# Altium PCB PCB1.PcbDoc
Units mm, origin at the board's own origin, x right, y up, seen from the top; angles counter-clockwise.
Board outline 69.22 x 64.13 mm, 4 copper layers (Top Layer, Int1 (GND), Int2 (PWR), Bottom Layer), stack 1.591 mm thick; 51 components, 53 nets, 197 pads, 100 vias.
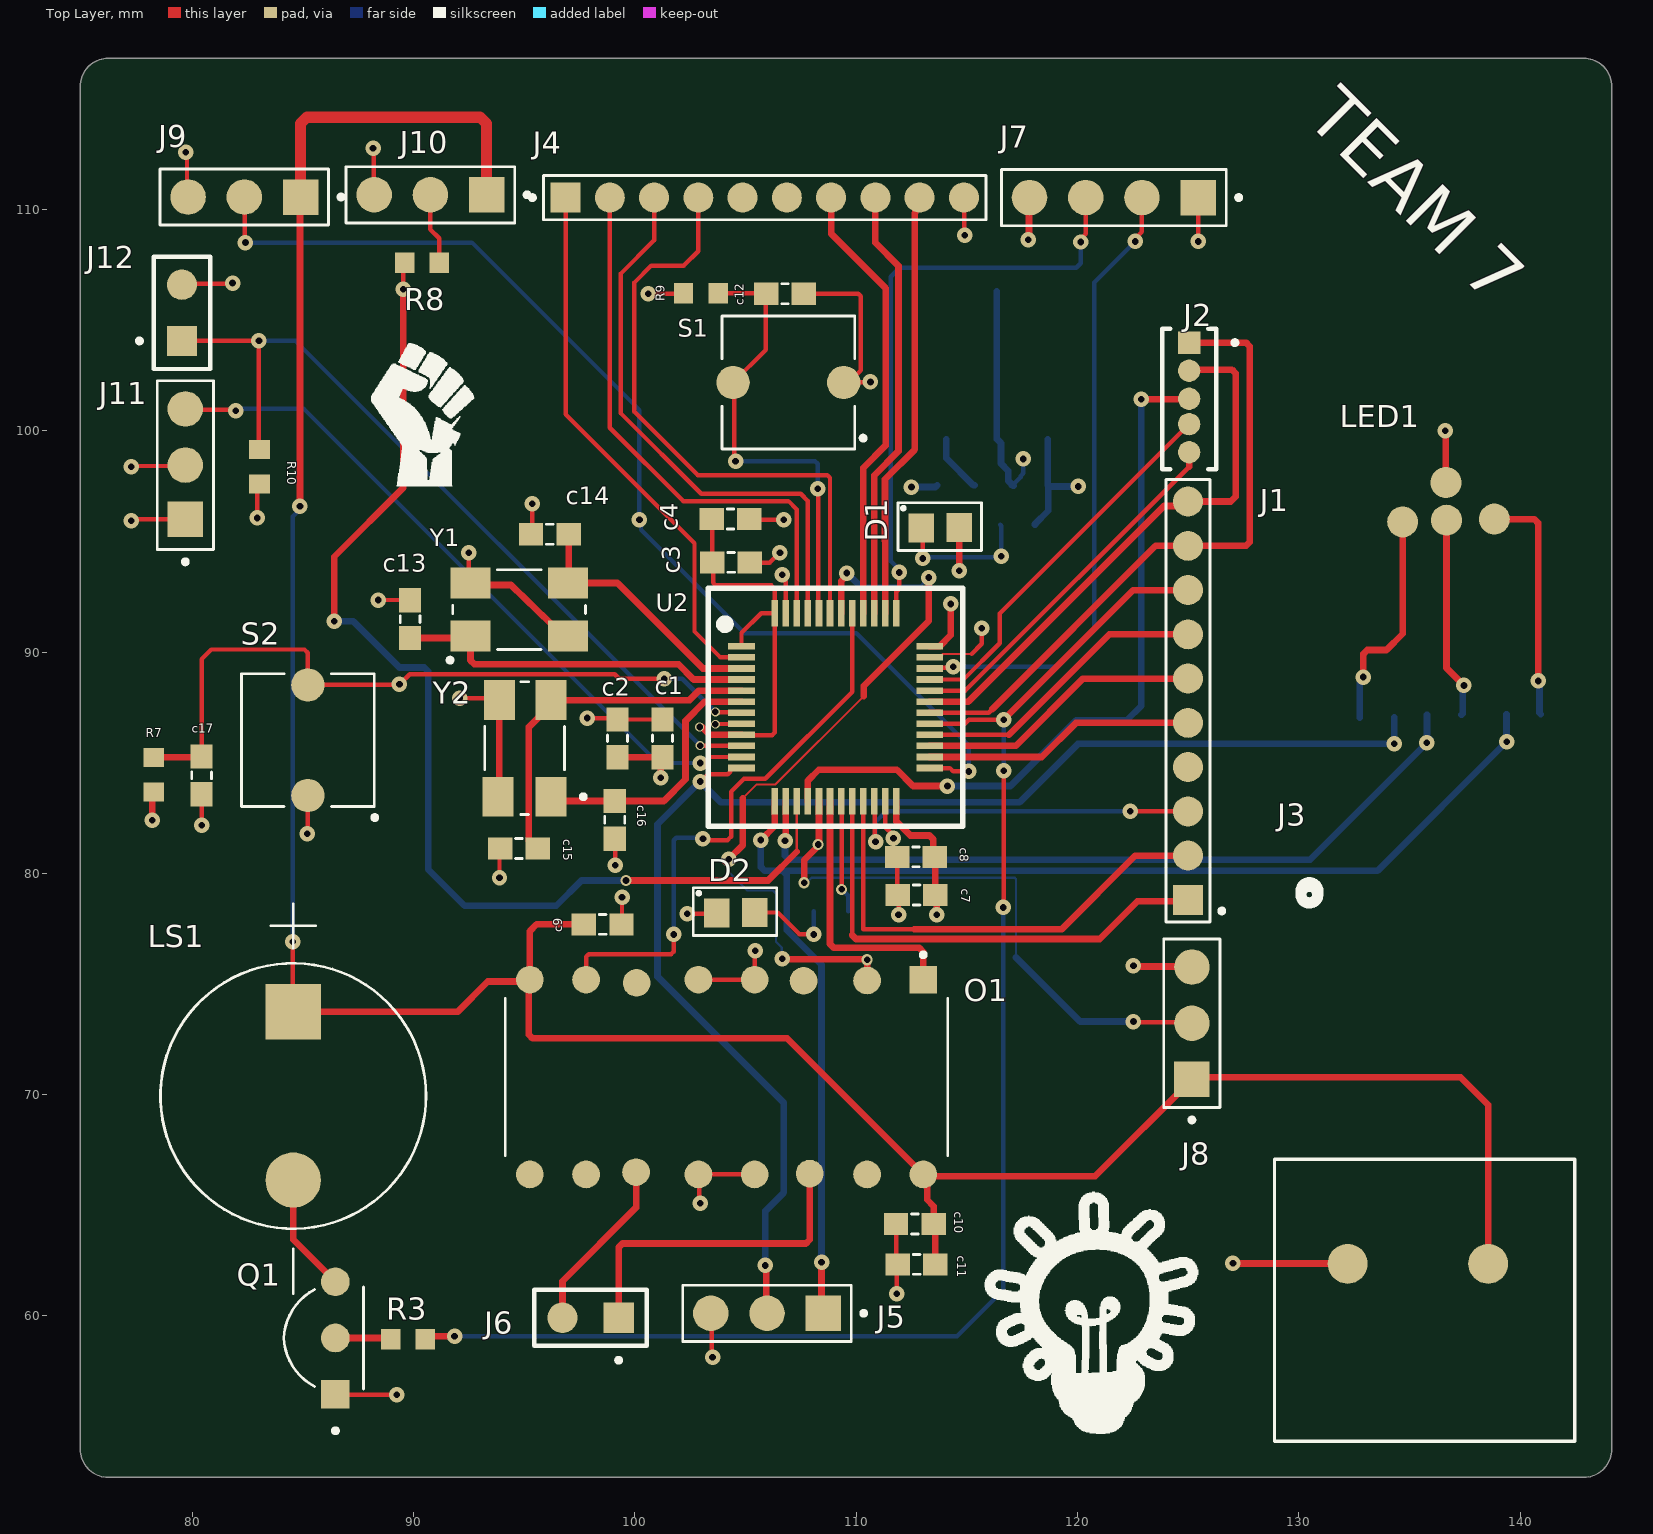
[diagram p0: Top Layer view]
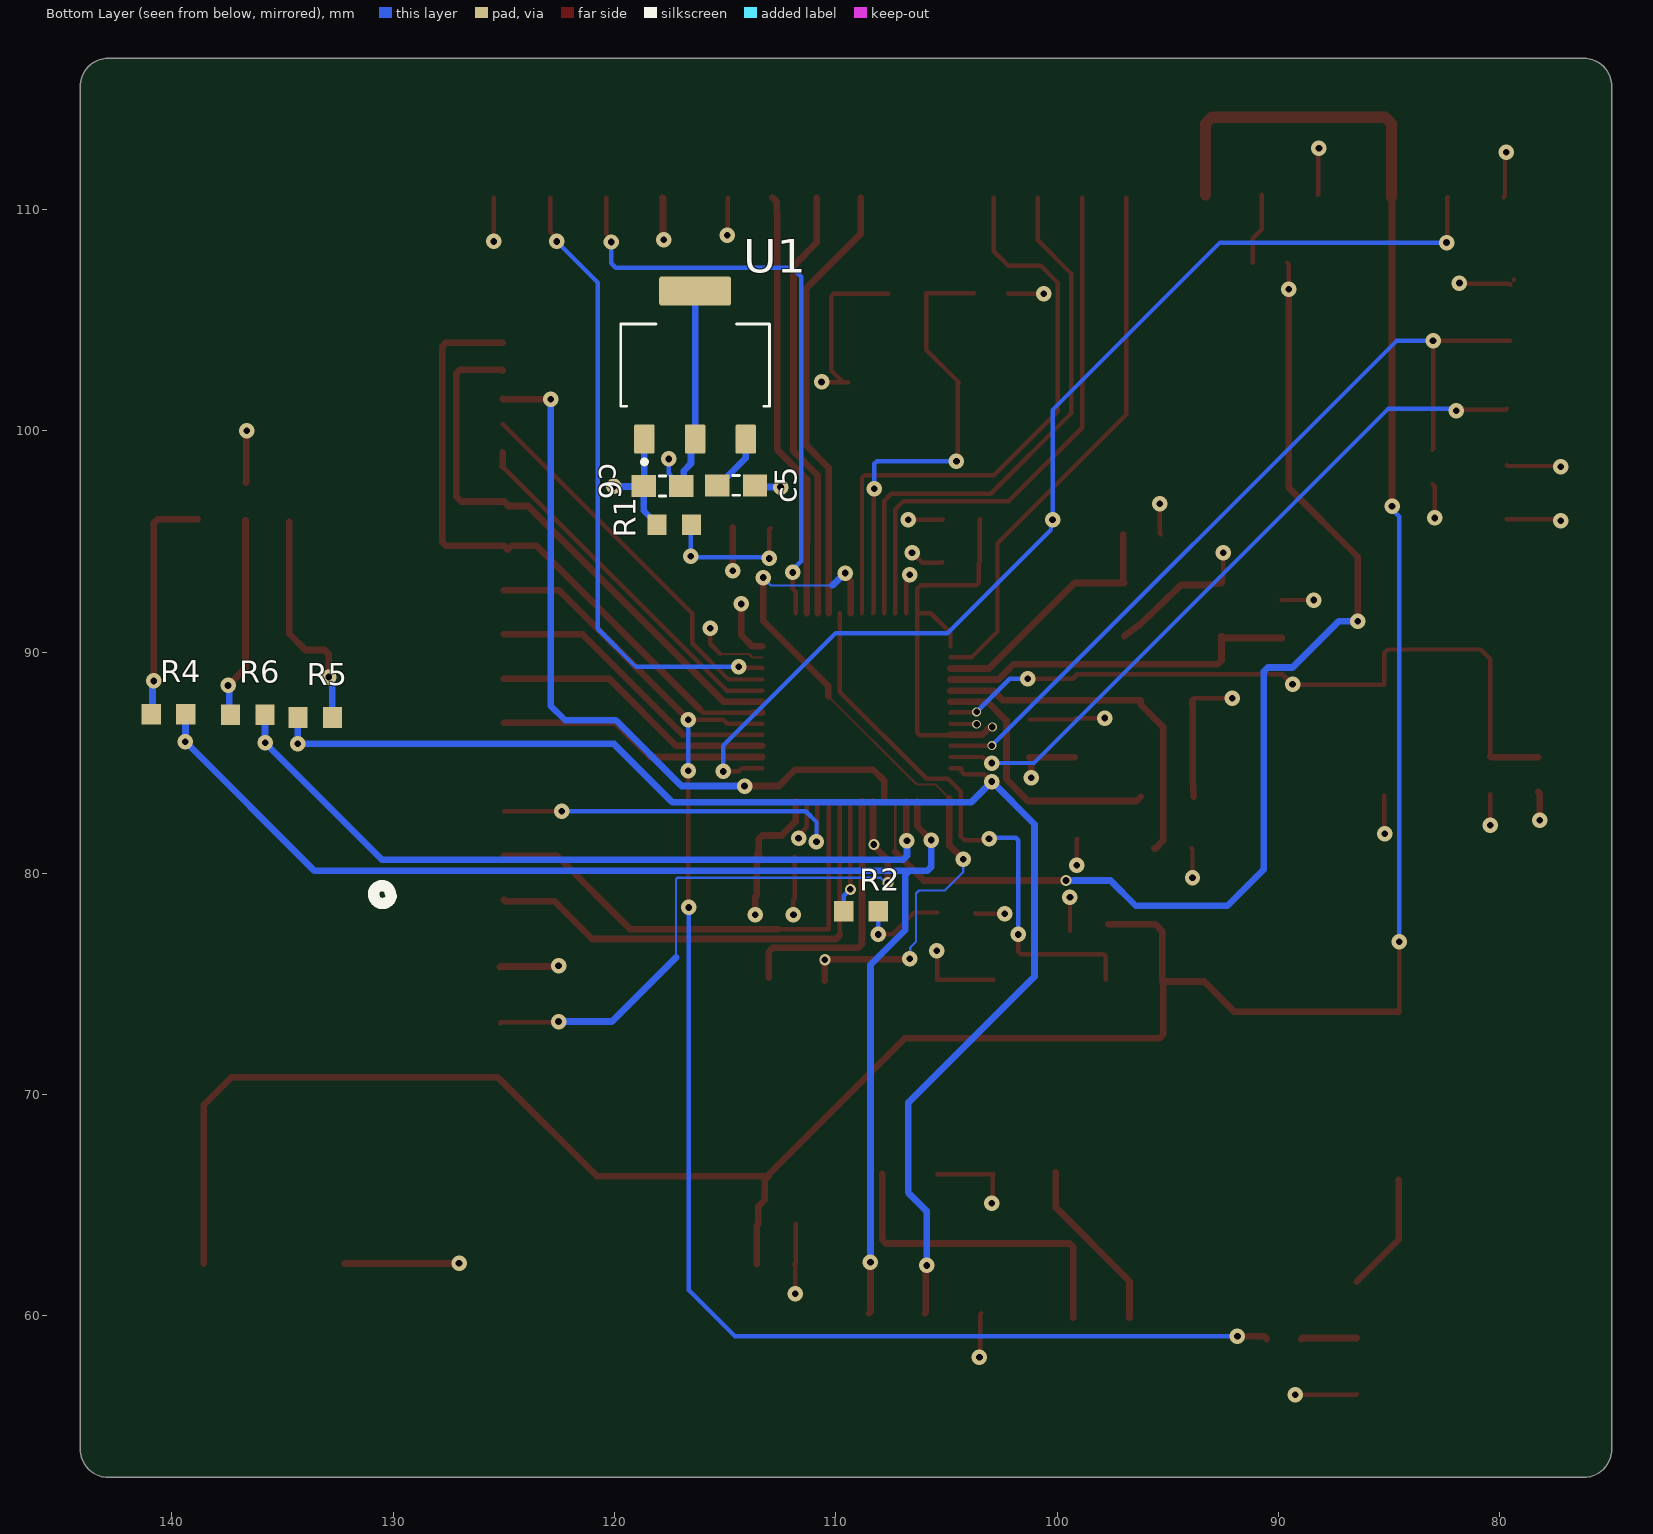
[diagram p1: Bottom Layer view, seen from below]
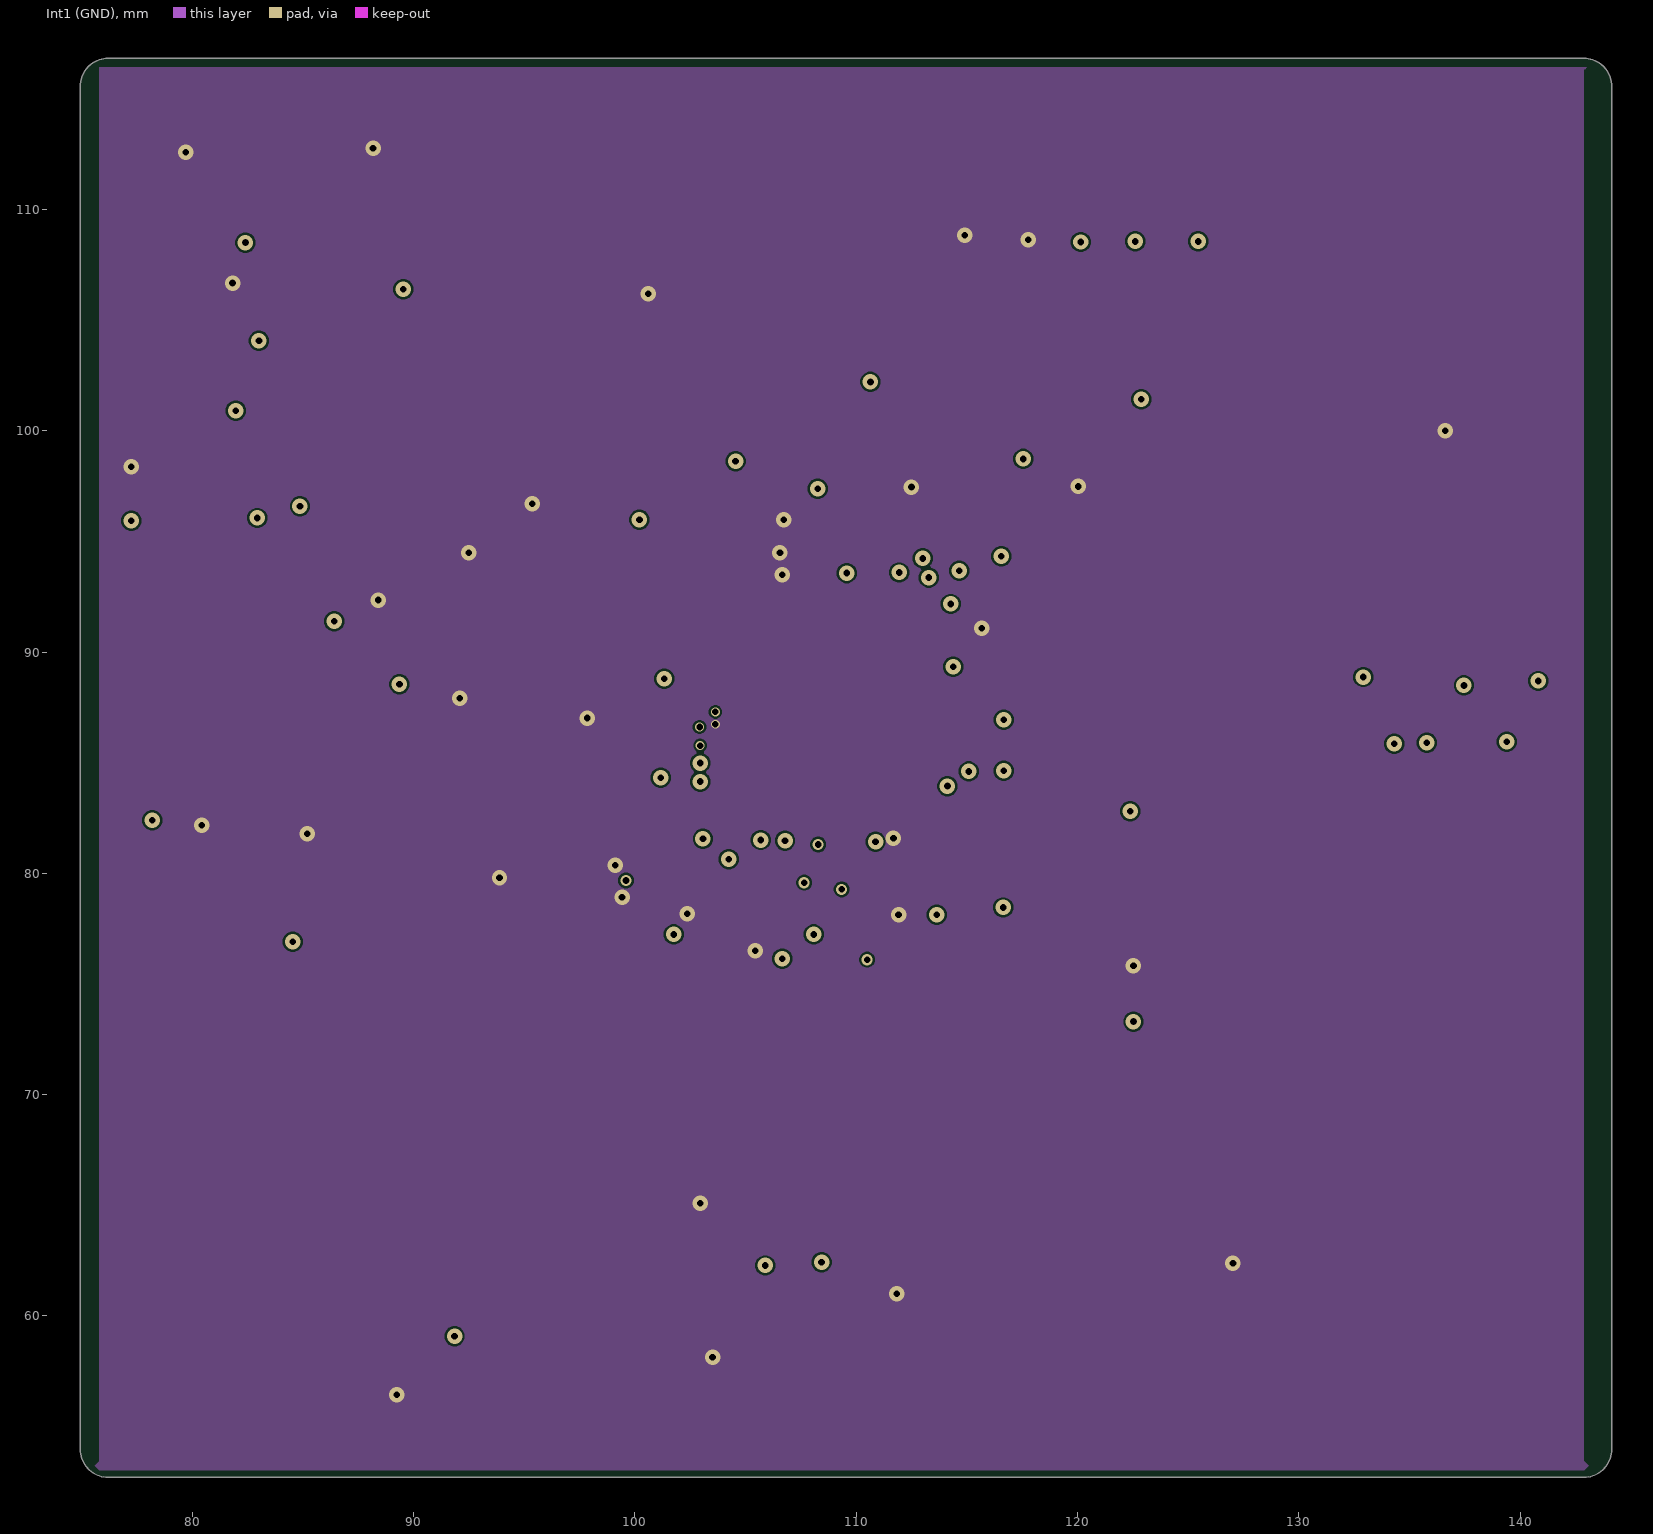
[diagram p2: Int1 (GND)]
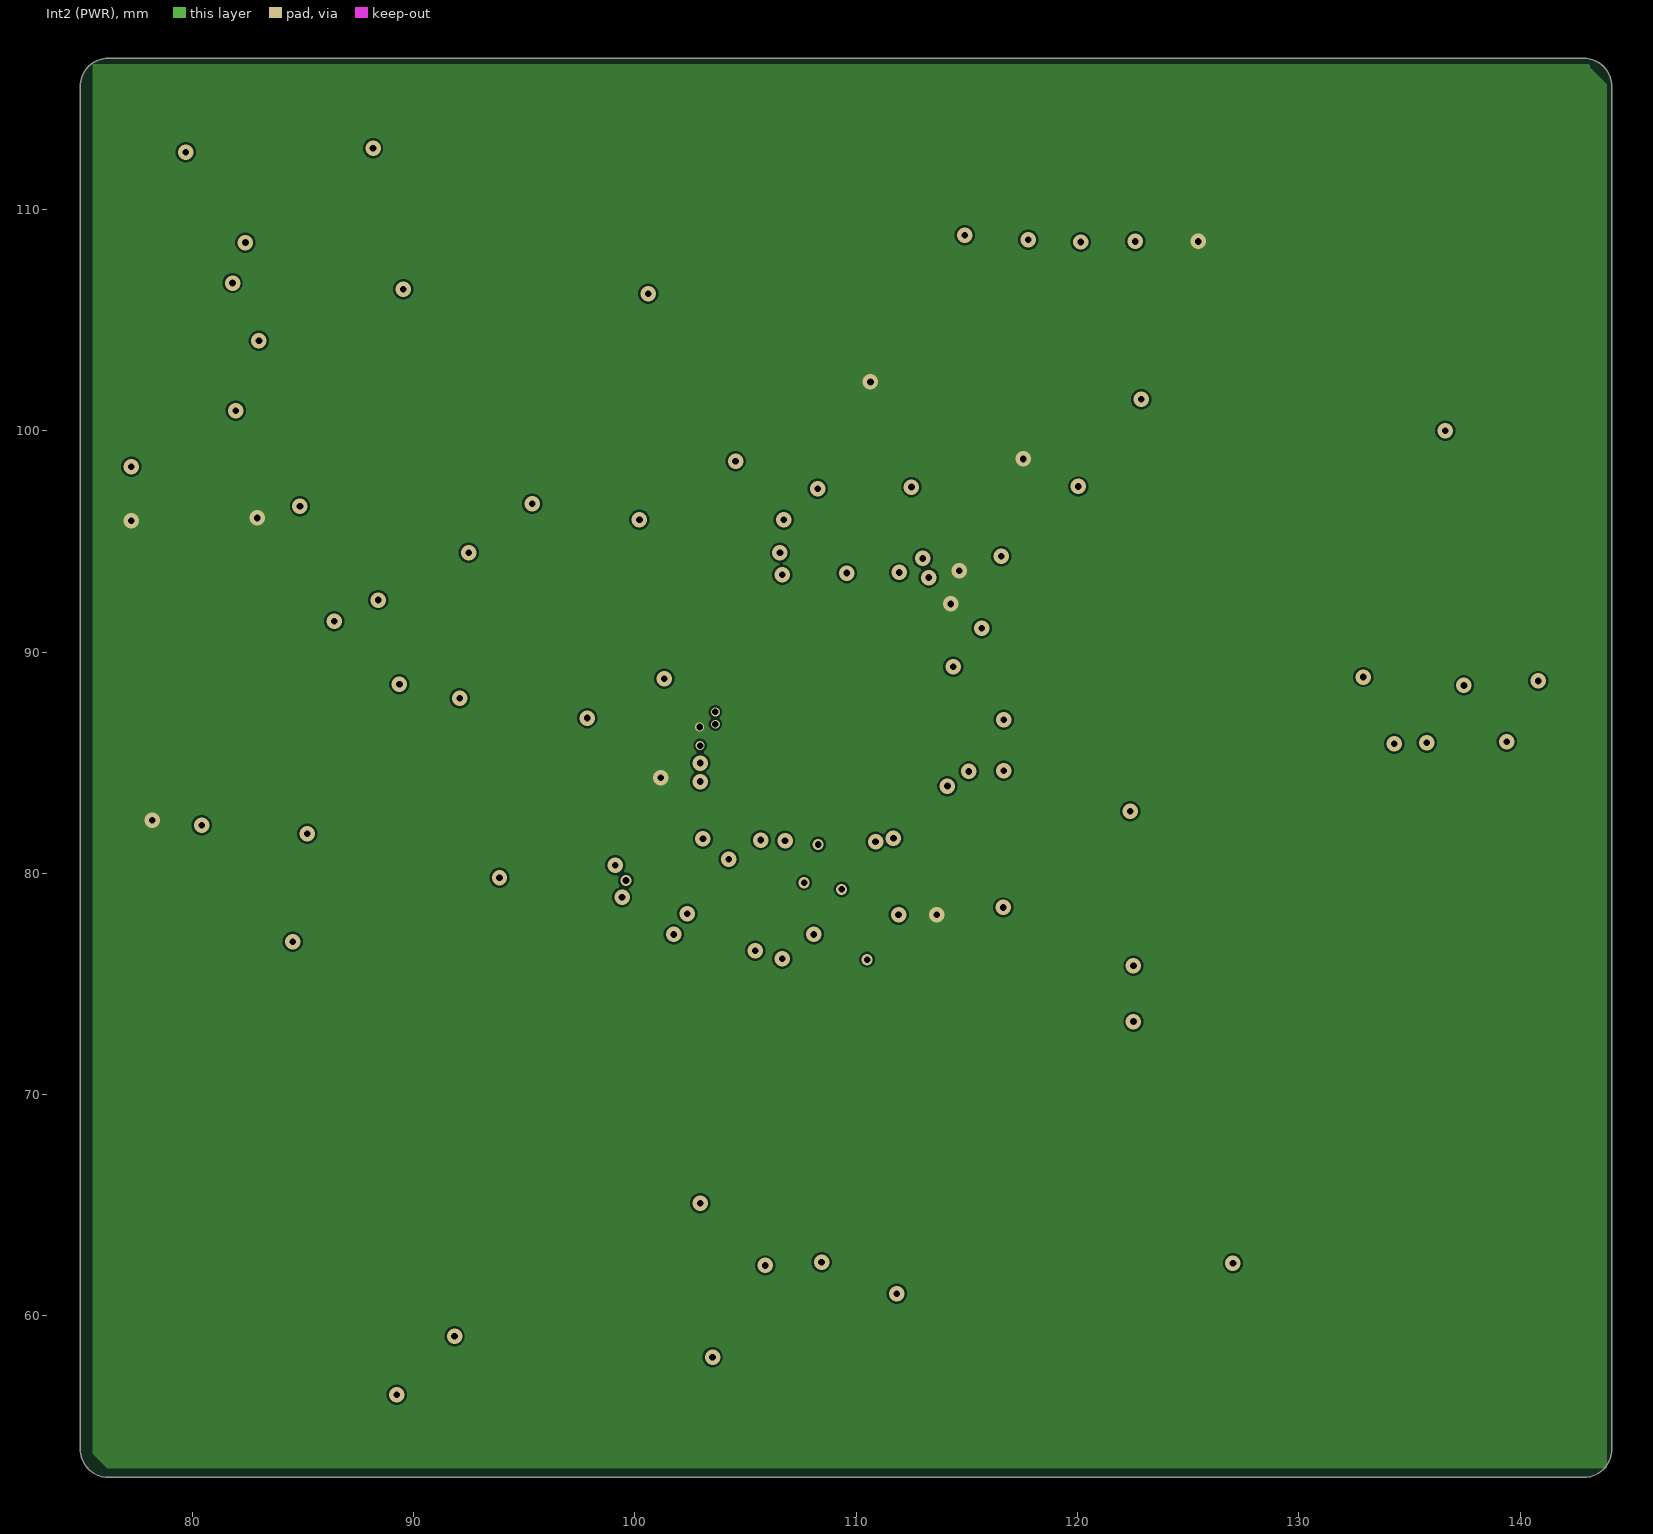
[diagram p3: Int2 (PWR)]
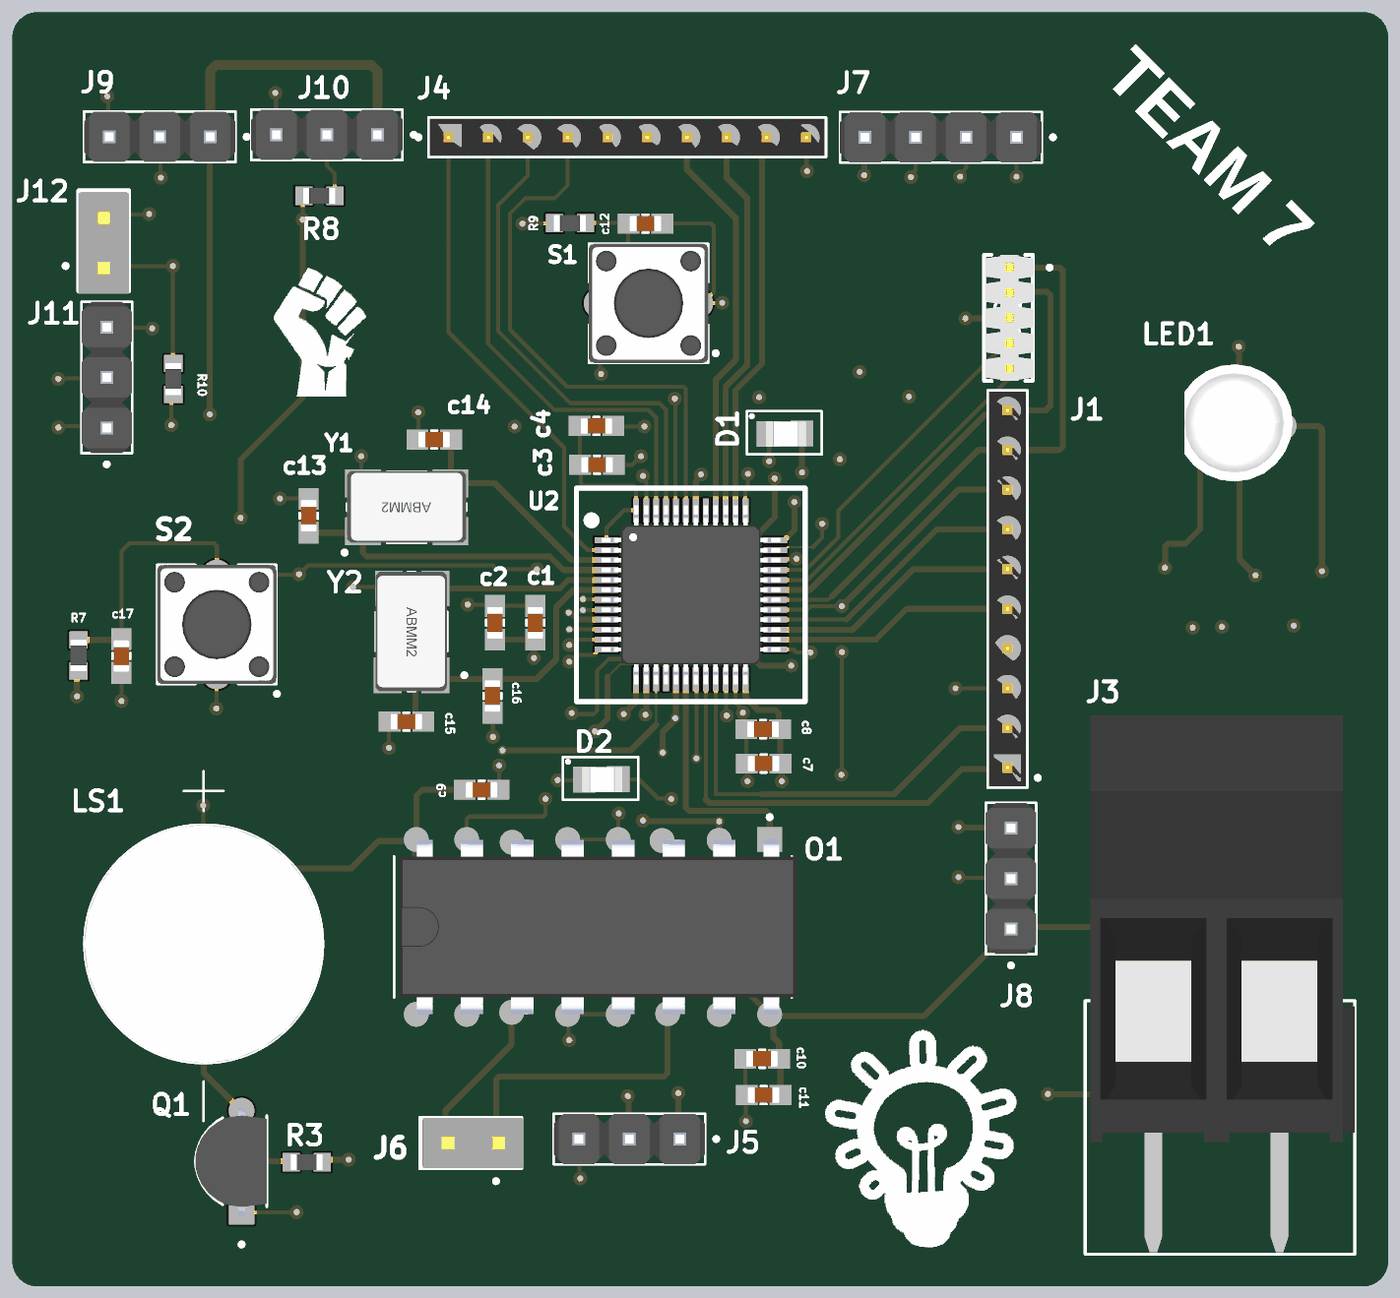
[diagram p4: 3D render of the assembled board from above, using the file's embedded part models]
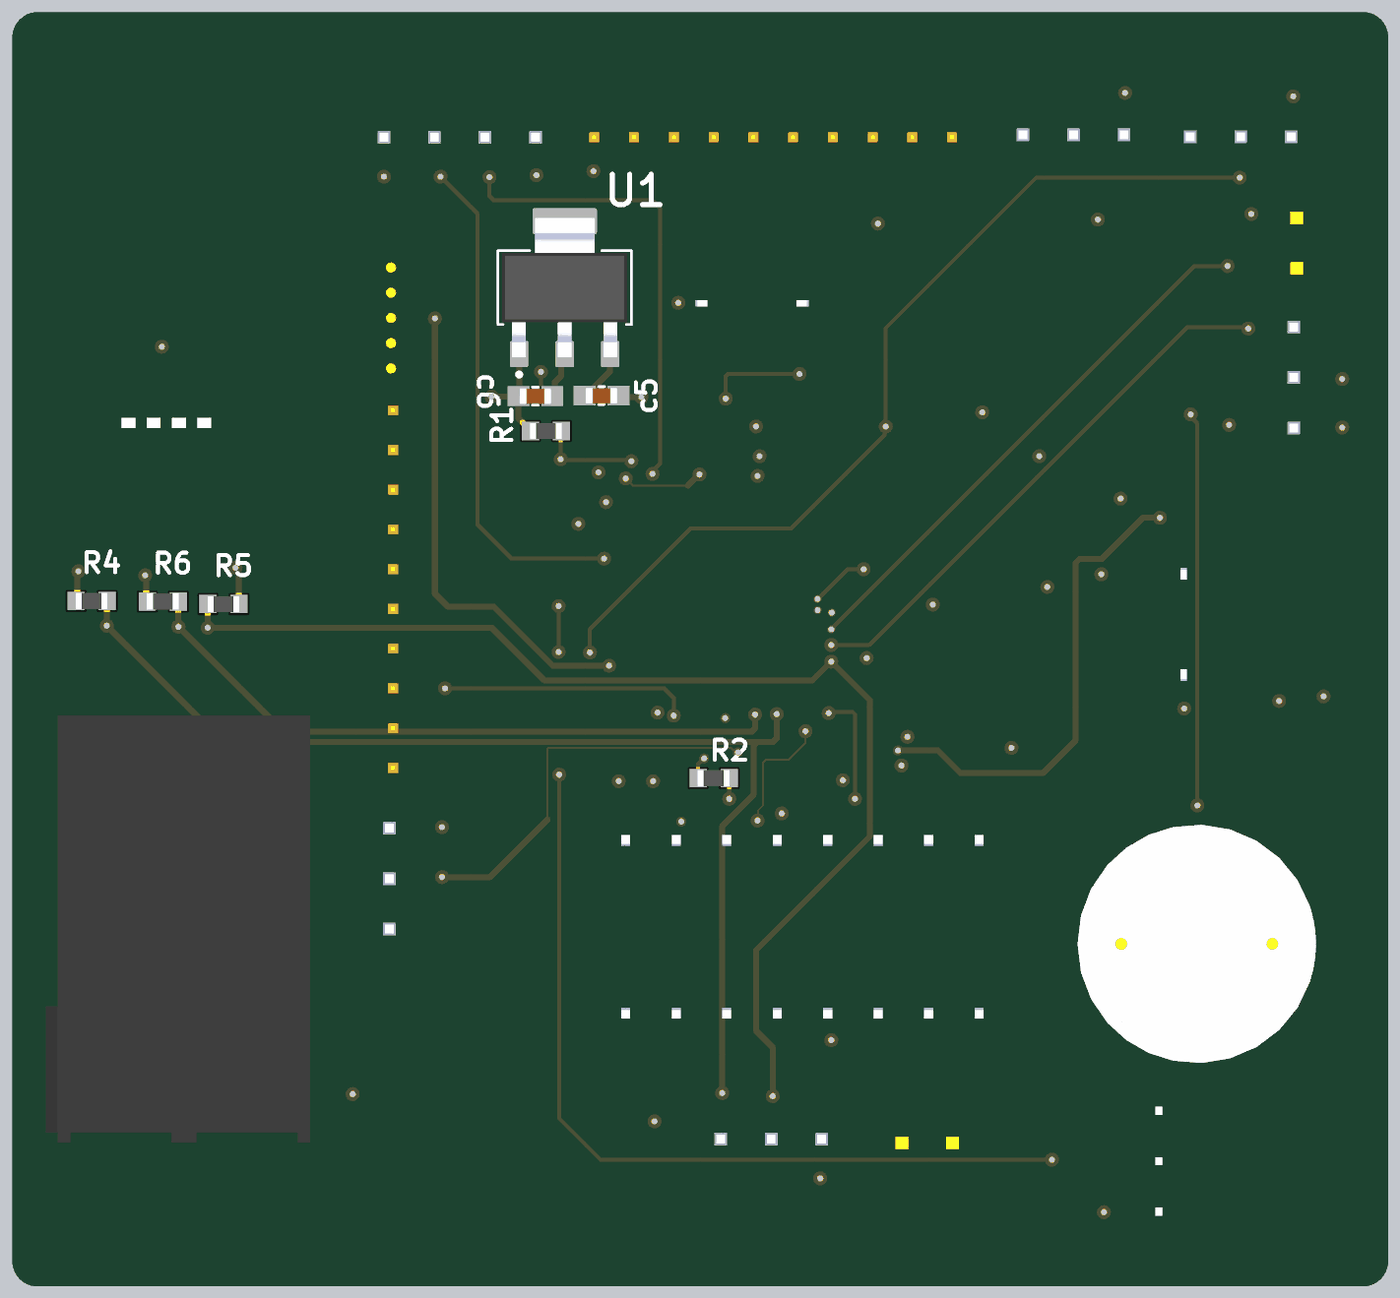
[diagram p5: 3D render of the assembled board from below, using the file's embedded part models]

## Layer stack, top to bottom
Top Solder: solder mask 0.0254, SM-001, Dk 4
Top Layer: signal copper 0.035
Dielectric 2: prepreg 0.2104, PP-017, Dk 4.3
Int1 (GND): signal copper 0.0175
Dielectric 3: core 1.065, Core-039, Dk 4.6
Int2 (PWR): signal copper 0.0175
Dielectric 4: prepreg 0.2104, PP-017, Dk 4.3
Bottom Layer: signal copper 0.035
Bottom Solder: solder mask 0.0254, SM-001, Dk 4

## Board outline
74.93,53.975 74.93,115.57 cw(c76.2,115.57) 76.2,116.84 142.875,116.84 cw(c142.875,115.57) 144.145,115.57 144.145,53.975 cw(c142.875,53.975) 142.875,52.705 76.2,52.705 cw(c76.2,53.975)

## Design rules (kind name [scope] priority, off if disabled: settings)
Clearance [All] p1: gap=0.1 ignorepadtopadclearanceinfootprint=FALSE
DiffPairsRouting [All] p1: maxlimit=0.254 minlimit=0.102 mostfreqgap=0.254 toplayer_minwidth=0.1 toplayer_maxwidth=0.381 toplayer_prefwidth=0.381 midlayer1_mingap=0.254 midlayer1_minwidth=0.381 midlayer1_maxwidth=0.381 midlayer1_prefwidth=0.381 midlayer2_mingap=0.254 midlayer2_minwidth=0.381 midlayer2_maxwidth=0.381 midlayer2_prefwidth=0.381 bottomlayer_mingap=0.254 bottomlayer_minwidth=0.381 bottomlayer_maxwidth=0.381 bottomlayer_prefwidth=0.381 maxuncoupledlength=12.7
MinimumSolderMaskSliver [All] p1: minsoldermaskwidth=0.1
PolygonConnect [All] p1: thpad.connectstyle=Relief thpad.reliefconductorwidth=0.254 thpad.reliefentries=4 thpad.polygonreliefangle="90 Angle" thpad.airgapwidth=0.254 smdpad.connectstyle=Direct smdpad.reliefconductorwidth=0.254 smdpad.reliefentries=4 smdpad.polygonreliefangle="90 Angle" smdpad.airgapwidth=0.254 via.connectstyle=Direct via.reliefconductorwidth=0.254 via.reliefentries=4 via.polygonreliefangle="90 Angle" via.airgapwidth=0.254
RoutingVias [All] p1: holewidth=0.3 width=0.7 viastyle="Through Hole" minholewidth=0.15 minwidth=0.25 maxholewidth=0.5 maxwidth=0.8
SilkToSilkClearance [All] p1: silktosilkclearance=0.08
SilkToSolderMaskClearance [IsPad] p1: minsilkscreentomaskgap=0.08 clearancetoexposedcopper=TRUE
SolderMaskExpansion [All] p1: expansion=0 istentingtop=FALSE
SupplyNets "Schematic Supply Nets_3" [InNet('+5')] p1: voltage=0.000
SupplyNets "Schematic Supply Nets_2" [InNet('3V3')] p2: voltage=0.000
SupplyNets "Schematic Supply Nets_1" [InNet('GND')] p3: voltage=0.000
SupplyNets "Schematic Supply Nets" [InNet('VBUS')] p4: voltage=0.000
Width [All] p1: maxlimit=2 minlimit=0.1 preferedwidth=0.3
26 further rules are at their usual default settings.

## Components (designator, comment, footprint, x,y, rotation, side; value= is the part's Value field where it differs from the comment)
c1 "C 10uf" CAPC1608X90 101.244,86.106 r270 top
c2 "C 100nf" CAPC1608X90 99.212,86.106 r270 top
c3 "C 100nf" CAPC1608X90 104.343,94.056 r180 top
c4 "C 100nf" CAPC1608X90 104.318,96.012 r180 top
c5 "C 10uf" CAPC1608X90 114.503,97.536 r0 bottom
c6 "C 10uf" CAPC1608X90 117.831,97.511 r180 bottom
c7 "C 1uf" CAPC1608X90 112.725,79.019 r0 top
c8 "C 10nf" CAPC1608X90 112.7,80.747 r0 top
c9 "C 0.1uF" CAPC1608X90 98.538,77.699 r180 top
c10 "C 0.1uF" CAPC1608X90 112.649,64.16 r180 top
c11 "C 100uf" CAPC1608X90 112.725,62.332 r180 top
c12 "C 100nf" CAPC1608X90 106.782,106.197 r0 top
c13 "C 12pf" CAPC1608X90 89.84,91.491 r270 top
c14 "C 12pf" CAPC1608X90 96.153,95.326 r0 top
c15 "C 20pf" CAPC1608X90 94.756,81.128 r0 top
c16 "C 20pf" CAPC1608X90 99.085,82.423 r90 top
c17 "C 100nf" CAPC1608X90 80.416,84.43 r90 top
D1 "7012X1" LED_7012X1 113.581,95.606 r0 top
D2 "YELLOW LED" LED_7012X1 104.335,78.207 r0 top
J1 "10 PIN HEADER" HARWIN_M22-2511005 124.993,87.804 r90 top
J2 "5 pin headres" SAMTEC_TMS-105-53-G-S 125.044,101.448 r270 top
J3 "ADAPTER 5V 2A" CONN2_0393800102_524X492_MOL 138.557,62.357 r0 top
J4 "10 PIN HEADER" HARWIN_M22-2511005 105.864,110.541 r0 top
J5 "3 PIN HEADER" HARWIN_M20-9990346#1 105.969,60.122 r180 top
J6 "DC MOTOR FAN BLADE" SAMTEC_MTSW-101-09-L-D-515 99.263,59.919 r90 top
J7 "4 PIN HEADER" HARWIN_M20-9990446 121.641,110.541 r180 top
J8 "SERVO" HARWIN_M20-9990346#1 125.171,73.228 r90 top
J9 "PIR SENSOR" HARWIN_M20-9990346#1 82.347,110.566 r180 top
J10 "GAS SENSOR" HARWIN_M20-9990346#1 90.754,110.668 r180 top
J11 "NTC module" HARWIN_M20-9990346#2 79.68,98.45 r90 top
J12 "LDR" SAMTEC_MTSW-101-09-L-D-515 79.527,104.064 r0 top
LED1 "RGB" L-154A4SUREQBFZGEC 136.652,96.291 r0 top
LS1 "BUZZER" XDCR_CMI-1210-5-95T 84.557,69.942 r270 top
O1 "L293D" DIP880W50P254L2000H510Q16 104.14,70.796 r270 top
Q1 "2N2222A" TO92254P470H750-3 84.132,59.004 r90 top
R1 "R220" RESC1608X55N 117.297,95.758 r180 bottom
R2 "R220" RESC1608X55N 108.864,78.283 r0 bottom
R3 "1k" RESC1608X55N 89.738,58.953 r180 top
R4 "R220" RESC1608X55N 140.157,87.198 r180 bottom
R5 "R220" RESC1608X55N 133.528,87.046 r180 bottom
R6 "R220" RESC1608X55N 136.576,87.173 r180 bottom
R7 "R10k" RESC1608X55N 78.257,84.462 r270 top
R8 "1k" RESC1608X55N 90.373,107.594 r0 top
R9 "R10k" RESC1608X55N 102.979,106.223 r0 top
R10 "R10k" RESC1608X55N 83.033,98.374 r90 top
S1 "BUTT-2" SW_BUTT-2 106.934,102.184 r0 top
S2 "BUTT-2" SW_BUTT-2 85.217,86.019 r90 top
U1 "AMS1117-3.3" SOT229P700X180-4N 116.357,102.972 r180 bottom
U2 "ST STM32F103C8T6" STM 109.065,87.511 r0 top
Y1 "32KHZ" XTAL_ABMM2-8.000MHZ-E2-T#1 94.767,91.923 r90 top
Y2 "8MHZ" XTAL_ABMM2-8.000MHZ-E2-T#2 95.015,85.664 r180 top

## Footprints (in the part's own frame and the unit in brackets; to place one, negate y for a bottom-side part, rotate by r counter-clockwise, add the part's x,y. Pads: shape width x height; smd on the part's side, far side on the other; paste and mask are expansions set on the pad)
CAPC1608X90 [mm]
  rect 1.1x1 smd: 1(-0.85,0) 2(0.85,0)
  silkscreen extent -0.15,-0.45 0.15,0.45, body extent -0.8,-0.4 0.8,0.4, height 0.87
CONN2_0393800102_524X492_MOL [mil]
  round 71 smd: 1(0,0) 2(-250,0)
  silkscreen extent -380,-316 154,678, body extent -370,-312 154,751, height 311
DIP880W50P254L2000H510Q16 [mm]
  rect 1.25x1.25 smd: 1(-4.4,8.89)
  round 1.25 smd: 2(-4.363,6.35) 3(4.363,3.759) 4(-4.4,1.27) 5(-4.4,-1.27) 6(4.298,-4.089) 7(-4.4,-6.35) 8(-4.4,-8.89) 9(4.4,-8.89) 10(4.4,-6.35) 11(-4.261,-4.064) 12(4.4,-1.27) 13(4.4,1.27) 14(-4.349,3.48) 15(4.4,6.35) 16(4.4,8.89)
  silkscreen extent -5.62,-10 3.55,10, body extent -4.62,-9.75 4.62,10.25, height 5.1
HARWIN_M20-9990346#1 [mm]
  rect 1.605x1.605 smd: 1(-2.54,0)
  round 1.605 smd: 2(0,0) 3(2.54,0)
  silkscreen extent -4.47,-1.27 3.81,1.27, body extent -3.81,-1.27 3.81,1.27, height 8.74
HARWIN_M20-9990346#2 [mm]
  rect 1.605x1.605 smd: 1(-2.438,0)
  round 1.605 smd: 2(0,0) 3(2.54,0)
  silkscreen extent -4.47,-1.27 3.81,1.27, body extent -3.81,-1.27 3.81,1.27, height 8.74
HARWIN_M20-9990446 [mm]
  rect 1.605x1.605 smd: 1(-3.81,0)
  round 1.605 smd: 2(-1.27,0) 3(1.27,0) 4(3.81,0)
  silkscreen extent -5.74,-1.27 5.08,1.27, body extent -5.08,-1.27 5.08,1.27, height 8.74
HARWIN_M22-2511005 [mm]
  rect 1.358x1.358 smd: 1(-9,0)
  round 1.358 smd: 2(-7,0) 3(-5,0) 4(-3,0) 5(-1,0) 6(1,0) 7(3,0) 8(5,0) 9(7,0) 10(9,0)
  silkscreen extent -10,-1.62 10,1, body extent -10,-1 10,1, height 3.5
L-154A4SUREQBFZGEC [mm]
  round 1.4 smd: 1(-1.956,-0.406) 2(0,1.372) 3(2.184,-0.279) 4(0.025,-0.33)
  body extent -2.75,-3.07 2.7,2.82, height 9.6
LED_7012X1 [mm]
  rect 1.15x1.3 smd: A(1.075,0.025) C(-0.635,0)
  silkscreen extent -1.7,-1.02 2.07,1.14, body extent -0.74,-0.62 1.27,0.62, height 0.73
RESC1608X55N [mm]
  rect 0.87x0.93 smd paste+0 mask+0.102: 1(-0.78,0) 2(0.78,0)
  body extent -0.8,-0.4 0.8,0.4, height 0.55
SAMTEC_MTSW-101-09-L-D-515 [mm]
  rect 1.37x1.37 smd: 01(0,0)
  round 1.37 smd: 02(0,2.54)
  silkscreen extent -2.02,-1.27 1.27,3.81, body extent -1.27,-1.4 1.27,3.68, height 15.62
SAMTEC_TMS-105-53-G-S [mm]
  rect 1.01x1.01 smd: 01(-2.54,0)
  round 1.01 smd: 02(-1.27,0) 03(0,0) 04(2.413,0) 05(1.143,0)
  silkscreen extent -3.18,-1.22 3.18,2.17, body extent -3.18,-1.17 3.18,1.27, height 9.78
SOT229P700X180-4N [mm]
  rrect15% 0.93x1.31 smd: 1(-2.29,-3.345) 2(0,-3.345) 3(2.29,-3.345)
  rrect15% 3.24x1.31 smd: 2(0,3.345)
  silkscreen extent -3.36,-4.47 3.36,1.86, body extent -3.15,-3.5 3.15,3.5, height 1.8
STM [mm]
  rect 1.2x0.3 smd mask+0.102: 1(-4.25,2.75) 2(-4.25,2.25) 3(-4.25,1.75) 4(-4.25,1.25) 5(-4.25,0.75) 6(-4.25,0.25) 7(-4.25,-0.25) 8(-4.25,-0.75) 9(-4.25,-1.25) 10(-4.25,-1.75) 11(-4.25,-2.25) 12(-4.25,-2.75) 25(4.25,-2.75) 26(4.25,-2.25) 27(4.25,-1.75) 28(4.25,-1.25) 29(4.25,-0.75) 30(4.25,-0.25) 31(4.25,0.25) 32(4.25,0.75) 33(4.25,1.25) 34(4.25,1.75) 35(4.25,2.25) 36(4.25,2.75)
  rect 0.3x1.2 smd mask+0.102: 13(-2.75,-4.25) 14(-2.25,-4.25) 15(-1.75,-4.25) 16(-1.25,-4.25) 17(-0.75,-4.25) 18(-0.25,-4.25) 19(0.25,-4.25) 20(0.75,-4.25) 21(1.25,-4.25) 22(1.75,-4.25) 23(2.25,-4.25) 24(2.75,-4.25) 37(2.75,4.25) 38(2.25,4.25) 39(1.75,4.25) 40(1.25,4.25) 41(0.75,4.25) 42(0.25,4.25) 43(-0.25,4.25) 44(-0.75,4.25) 45(-1.25,4.25) 46(-1.75,4.25) 47(-2.25,4.25) 48(-2.75,4.25)
  silkscreen extent -5.75,-5.38 5.75,5.37, body extent -4.5,-4.5 4.5,4.5, height 1.6
SW_BUTT-2 [mm]
  round 1.508 smd mask+0.102: 1(-2.5,0) 2(2.5,0)
  silkscreen extent -3,-3 3.48,3, body extent -3,-3 3,3, height 5.1
TO92254P470H750-3 [mm]
  rect 1.298x1.298 smd mask+0.102: 1(-2.54,-2.33)
  round 1.298 smd mask+0.102: 2(0,-2.33) 3(2.54,-2.33)
  silkscreen extent -4.29,-3.6 2.3,0, body extent -2.74,-3.6 2.74,0, height 8.09
XDCR_CMI-1210-5-95T [mm]
  round 2.5 smd: N(3.8,0)
  rect 2.5x2.5 smd: P(-3.8,0)
  silkscreen extent -8.69,-6 8.92,6, body extent -6,-6 6,6, height 7
XTAL_ABMM2-8.000MHZ-E2-T#1 [mm]
  rect 1.4x1.8 smd: 1(-1.2,2.2) 2(-1.2,-2.2) 3(1.2,-2.2) 4(1.2,2.2)
  silkscreen extent -2.39,-3 1.8,3.22, body extent -1.78,-3 1.82,3, height 1.2
XTAL_ABMM2-8.000MHZ-E2-T#2 [mm]
  rect 1.4x1.8 smd: 1(-1.2,2.2) 2(1.137,-2.169) 3(-1.2,-2.169) 4(1.2,2.2)
  silkscreen extent -2.75,-3 1.8,3, body extent -1.78,-3 1.82,3, height 1.2

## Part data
c1 c5 c6: "10uF Â±10% 50V Ceramic Capacitor X7R 0603 (1608 Metric)", Package="0603 KEMET"
c2 c3 c4 c12 c17: "100nF Â±10% 50V Ceramic Capacitor X7R 0603 (1608 Metric)", Package="0603 KEMET"
c7: "1uF Â±10% 50V Ceramic Capacitor X7R 0603 (1608 Metric)", Package="0603 KEMET"
c8: "10nF Â±10% 50V Ceramic Capacitor X7R 0603 (1608 Metric)", Package="0603 KEMET"
c9 c10: "0.1uFÂ±10% 50V Ceramic Capacitor X7R 0603 (1608 Metric)", Package="0603 KEMET"
c11: "100uf Â±10% 50V Ceramic Capacitor X7R 0603 (1608 Metric)", Package="0603 KEMET"
c13 c14: "12PF Â±10% 50V Ceramic Capacitor X7R 0603 (1608 Metric)", Package="0603 KEMET"
c15 c16: "20PF Â±10% 50V Ceramic Capacitor X7R 0603 (1608 Metric)", Package="0603 KEMET"
D1: "Red - LED Indication - Discrete 1.7V 0805 (2012 Metric)"
D2: "Red 617nm Yellow LED Indication - Discrete 2V Radial", Package="Radial Kingbright"
J1 J4: "2.00mm (0.079\") Pitch SIL Vertical 2.4mm Throughboard Pin Header, 3.5mm mating pin height, gold, 10 contacts", Package=None
J2: Package=None
J3: library part "Power place", "2 Position Wire to Board Terminal Block Horizontal with Board 0.250\" (6.35mm) Through Hole", Package=None
J5: "2.54mm (0.1) Pitch SIL Vertical Throughboard Pin Header, 6.1mm mating pin height, tin, 3 contacts", Package=None
J6 J12: library part "2 pin Headers", Manufacturer=Harwin, Package=None, Suoolier part number=952-1902-ND
J7: library part "4 Pin headers", "1kV 1 2.54mm Pin Header 3A 2.5mm Through Hole 6mm -40℃~+105℃ 3mm Gold 4P 1x4P Through Hole,P=2.54mm Headers, Male Pins", Package=None
J8 J9 J10 J11: library part "3 PIN HEADER", "2.54mm (0.1) Pitch SIL Vertical Throughboard Pin Header, 6.1mm mating pin height, tin, 3 contacts", Package=None
LED1: "Red, Green, Blue (RGB) 630nm Red, 525nm Green, 465nm Blue LED Indication - Discrete 1.9V Red, 3.3V Green, 3.3V Blue Radial - 4 Leads", Package="Radial-4 Kingbright"
LS1: "12 mm, 5 Vdc, 98 dB, Through Hole, Magnetic Audio Indicator Buzzer", Package=None
Q1: "BJT, TO-92, 40V, 600mA, NPN, 0.625W, 150Â°C", Package="TO-92 Diotec"
R1 R2 R4 R5 R6: "RES, 220OHM, 1%, 0.1W, 0603, THICK FILM; Resistance: 10kohm; Resistance Tolerance: Â± 1%; Power Rating: 100mW; Resistor Case / Package: 0603 ^1608 Metric]; Resistor Technology: Thick Film; Resistor Type: Genera 67AK7947", Package="0603-2 Vishay"
R3 R8: "RES, 1K, 1%, 0.1W, 0603, THICK FILM; Resistance: 10kohm; Resistance Tolerance: Â± 1%; Power Rating: 100mW; Resistor Case / Package: 0603 ^1608 Metric]; Resistor Technology: Thick Film; Resistor Type: Genera 67AK7947", Package="0603-2 Vishay"
R7 R9 R10: "RES, 10K, 1%, 0.1W, 0603, THICK FILM; Resistance: 10kohm; Resistance Tolerance: Â± 1%; Power Rating: 100mW; Resistor Case / Package: 0603 ^1608 Metric]; Resistor Technology: Thick Film; Resistor Type: Genera 67AK7947", Package="0603-2 Vishay"
S1 S2: "Tactile Switches MINI PUSH BUTTON SWITCH 2-PIN QTY. 4", Package=None
U1: "Linear Voltage Regulator IC Positive Fixed 1 Output 1A SOT-223-3L", Package="SOT-223-3L UMW"
U2: "Medium-density performance line Arm-based 32-bit MCU with 64 or 128 KB Flash, USB, CAN, 7 timers, 2 ADCs, 9 com. interfaces", Manufacturer=ST, MPN=STM32F103C8T6
Y1: library part "CRYSTAL 32KHZ", "32KHz Â±20ppm Crystal 12.5pF 72 Ohms 4-SMD, No Lead", Package="SMD-4 Abracon"
Y2: library part "CRYSTAL 8MHZ", "8 MHz Â±20ppm Crystal 18pF 72 Ohms 4-SMD, No Lead", Package="SMD-4 Abracon"

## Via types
v1: diameter 0.7, hole 0.3, Top Layer to Bottom Layer, tented both sides, 91 vias
v2: diameter 0.5, hole 0.3, Top Layer to Bottom Layer, tented both sides, 5 vias
v3: diameter 0.4, hole 0.3, Top Layer to Bottom Layer, tented both sides, 4 vias

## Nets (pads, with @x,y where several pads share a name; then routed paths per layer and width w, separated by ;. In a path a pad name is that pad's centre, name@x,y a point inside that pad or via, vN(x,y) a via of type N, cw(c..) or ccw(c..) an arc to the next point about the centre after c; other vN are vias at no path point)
3V3: c1.2 c2.2 c3.2 c4.2 c6.2 c7.2 c8.2 c12.2 D1.A J7.1 J11.1 R7.2 R10.1 S1.2 U1.2 U2.1 U2.9 U2.24 U2.36 U2.48 | length 58.3
  Top Layer w0.2: v1(77.241,95.936) 77.318,96.012 J11.1 ; v1(82.931,96.063) 82.931,97.493 R10.1 ; c4.2 103.493,95.987 c3.2 103.53,94.019 103.53,93.132 103.648,93.015 106.172,93.015 106.315,92.872 U2.48 ; U2.9 104.827,86.249 106.198,86.249 106.315,86.366 U2.48 ; U2.1 104.815,90.87 105.706,91.761 U2.48 ; c12.2 110.093,106.197 110.211,106.08 110.211,102.732 S1.2@109.662,102.184 ; S1.2 109.447,102.197 110.63,102.197 v1(110.642,102.21) ; v1(125.451,108.56) J7.1
  Top Layer w0.3: v1(78.181,82.398) 78.181,83.606 R7.2 ; c2.2 c1.2 101.168,85.18 v1(101.168,84.328) ; v3(102.921,86.614) 103.029,86.614 103.382,86.261 U2.9 ; U2.24 111.815,82.343 112.446,81.712 113.311,81.712 113.487,81.536 113.487,80.962 113.538,80.911 113.462,80.835 c8.2 113.563,80.733 c7.2@113.563,79.019 ; U2.36 113.765,90.261 114.275,90.771 v1(114.275,92.177) ; c7.2 113.64,78.954 v1(113.64,78.13) ; v1(114.656,93.675) D1.A
  Bottom Layer w0.2: c6.2 117.031,97.511 117.431,97.911 117.431,97.961 117.55,98.08 117.55,98.728 v1(117.551,98.73)
  Bottom Layer w0.3: U1.2@116.357,106.317 116.357,99.627 116.54,99.444 116.54,98.522 116.865,98.196 116.865,97.753 c6.2@117.108,97.511
+5: c9.2 c10.1 c11.1 J3.1 J8.1 J9.1 J10.1 LS1.P O1.8 O1.16 | length 130.5
  Top Layer w0.2: v1(84.531,76.911) 84.531,73.767 LS1.P ; J9.1@84.861,110.541 J9.1
  Top Layer w0.3: LS1.P 91.979,73.742 93.351,75.114 95.25,75.114 O1.8 ; v1(84.861,96.596) J9.1@84.861,110.541 ; c9.2 95.555,77.699 95.25,77.394 O1.8 ; O1.16 106.883,72.542 95.375,72.542 95.199,72.718 95.199,75.145 O1.8 ; c11.1 113.575,64.084 c10.1 113.499,64.961 113.212,65.249 113.212,66.132 113.03,66.314 120.797,66.314 J8.1 125.273,70.79 137.312,70.79 138.557,69.545 J3.1
  Top Layer w0.5: J9.1 84.887,113.88 85.18,114.173 93.001,114.173 93.294,113.88 J10.1
  Bottom Layer w0.2: v1(84.531,76.911) 84.531,96.131 84.861,96.461 v1(84.861,96.596)
BOOT0: c12.1 R9.2 S1.1 U2.44 | length 21
  Top Layer w0.2: R9.2 c12.1@105.906,106.223 ; v1(104.546,98.628) 104.49,98.684 104.49,102.128 S1.1 105.906,103.656 c12.1@105.906,106.223 ; c12.1 c12.1@105.906,106.223 ; v1(108.255,97.384) 108.285,97.353 108.285,91.791 U2.44
  Bottom Layer w0.2: v1(104.546,98.628) 108.138,98.628 108.255,98.511 v1(108.255,97.384)
BOOT1: J1.1 U2.20 | length 22
  Top Layer w0.2: 109.815,77.214 U2.20
  Top Layer w0.3: 109.815,77.214 109.991,77.038 121.006,77.038 122.707,78.74 124.929,78.74 J1.1
"FAN A": J6.01 O1.3 | length 14.9
  Top Layer w0.3: J6.01 99.263,63.096 99.439,63.271 107.723,63.271 107.899,63.447 O1.3
"FAN B": J6.02 O1.6 | length 8
  Top Layer w0.3: J6.02 96.723,61.57 100.051,64.897 O1.6
GND: c1.1 c2.1 c3.1 c4.1 c5.1 c6.1 c7.1 c8.1 c9.1 c10.2 c11.2 c13.1 c14.1 c15.1 c16.1 c17.1 D2.C J3.2 J4.10 J5.3 J7.4 J8.3 J9.3 J10.3 J11.2 J12.02 LED1.2 O1.4 O1.5 O1.12 O1.13 Q1.1 R1.1 R9.1 S2.1 U1.1 U2.8 U2.23 U2.35 U2.47 Y1.2 Y1.4 Y2.2 Y2.4 | length 88.5
  Top Layer w0.1: U2.35 113.765,89.761 113.92,89.916 115.214,89.916
  Top Layer w0.2: v1(77.241,98.374) 77.279,98.412 79.642,98.412 J11.2 ; J12.02@79.35,106.832 J12.02@79.362,106.82 ; J12.02@79.515,106.617 J12.02 79.566,106.642 81.775,106.642 v1(81.813,106.68) ; v1(79.705,112.598) 79.756,112.547 79.756,110.617 J9.3 ; v1(80.416,82.169) c17.1 ; v1(85.192,81.788) 85.204,81.801 85.204,83.506 S2.1 ; Q1.1 86.487,56.439 v1(89.23,56.439) ; v1(88.163,112.776) 88.189,112.751 88.189,110.693 J10.3 ; v1(88.392,92.354) 89.826,92.354 c13.1 ; v1(92.075,87.909) 93.802,87.909 Y2.2 ; v1(92.481,94.488) 92.481,93.209 Y1.4 ; v1(93.878,79.807) 93.878,81.1 c15.1 ; c14.1 95.352,95.375 v1(95.352,96.698) ; v1(97.841,87.02) 99.148,87.02 c2.1 c1.1 ; c16.1 99.111,81.548 v1(99.111,80.366) ; c9.1@99.416,77.417 v1(99.416,78.918) ; v1(100.598,106.197) 102.174,106.197 R9.1 ; v1(102.362,78.181) 103.674,78.181 D2.C ; O1.5 O1.4 105.423,75.208 105.423,76.492 v1(105.435,76.505) ; v1(102.946,65.1) 102.908,65.138 102.908,66.358 O1.12 O1.13 ; J5.3 103.467,60.084 103.467,58.179 v1(103.505,58.141) ; v3(103.632,86.741) 103.642,86.751 104.805,86.751 U2.8 ; c4.1 105.193,95.987 v1(106.731,95.987) ; c3.1 105.213,94.037 106.085,94.037 106.536,94.488 v1(106.553,94.488) ; v1(106.655,93.497) 106.655,93.362 106.815,93.202 U2.47 ; U2.23 111.315,82.089 111.684,81.72 v1(111.684,81.585) ; c10.2 111.799,62.408 c11.2 111.836,62.293 v1(111.836,61.011) ; c8.1 111.85,78.855 111.912,78.793 v1(111.912,78.13) ; J4.10 114.887,110.518 114.887,108.862 v1(114.91,108.839) ; 115.214,89.916 115.672,90.373 v1(115.672,91.084)
  Top Layer w0.3: Y1.4 93.317,93.033 94.397,93.033 96.217,91.273 Y1.2 ; Y2.4 93.868,84.214 93.868,87.083 Y2.2 ; v1(117.78,108.636) 117.805,108.661 117.805,110.515 J7.4 ; v1(122.53,75.819) 122.555,75.794 125.146,75.794 J8.3 ; v1(127.025,62.382) 127.038,62.37 132.194,62.37 J3.2 ; v1(136.627,100) 136.639,99.987 136.639,97.676 LED1.2
  Bottom Layer w0.3: v1(112.497,97.46) 113.577,97.46 c5.1 ; R1.1 118.077,95.788 118.681,96.391 c6.1 ; U1.1 118.647,97.544 c6.1 ; v1(120.04,97.485) 118.706,97.485 c6.1
NetD1_C: D1.C R1.2 | length 6.4
  Top Layer w0.2: D1.C 113.005,95.547 v1(113.005,94.234)
  Bottom Layer w0.2: v1(113.005,94.234) 113.055,94.285 116.51,94.285 v1(116.561,94.336) 116.561,95.715 R1.2
NetD2_A: D2.A R2.1 | length 4.1
  Top Layer w0.2: D2.A 106.451,78.232 107.427,77.256 108.062,77.256 v1(108.077,77.241)
  Bottom Layer w0.2: v1(108.077,77.241) 108.077,78.275 R2.1
NetJ10_2: J10.2 R8.2 | length 3.2
  Top Layer w0.2: J10.2 90.754,109.104 91.153,108.705 R8.2
NetLED1_1: LED1.1 R5.2 | length 10.2
  Top Layer w0.3: v1(132.918,88.875) 132.918,89.918 133.094,90.094 133.96,90.094 134.696,90.83 LED1.1
  Bottom Layer w0.3: R5.2 132.748,88.596 132.918,88.766 v1(132.918,88.875)
NetLED1_3: LED1.3 R4.1 | length 10.7
  Top Layer w0.3: LED1.3 140.642,96.012 140.818,95.836 v1(140.818,88.697)
  Bottom Layer w0.3: v1(140.818,88.697) 140.877,88.637 140.877,87.258 R4.1
NetLED1_4: LED1.4 R6.1 | length 9.2
  Top Layer w0.3: LED1.4 136.677,89.281 v1(137.465,88.494)
  Bottom Layer w0.3: R6.1 137.41,87.227 137.41,88.439 v1(137.465,88.494)
NetLS1_N: LS1.N Q1.3 | length 5.4
  Top Layer w0.3: LS1.N 84.557,63.449 Q1.3
NetQ1_2: Q1.2 R3.2 | length 2.5
  Top Layer w0.3: Q1.2 88.907,59.004 R3.2
NRST: c17.2 R7.1 S2.2 U2.7 | length 33.6
  Top Layer w0.2: c17.2 80.416,89.687 80.848,90.119 85.065,90.119 85.217,89.967 S2.2 85.23,88.532 89.344,88.532 v1(89.357,88.544) 89.362,88.544 89.819,89.002 99.085,89.002 99.289,88.798 v1(101.321,88.798) ; v3(103.632,87.3) 103.651,87.28 104.796,87.28 U2.7
  Top Layer w0.3: R7.1 80.379,85.242 c17.2
  Bottom Layer w0.2: v1(101.321,88.798) 102.133,88.798 v3(103.632,87.3)
OSC32_IN: c13.2 U2.4 Y1.1 | length 16.5
  Top Layer w0.3: c13.2 92.486,90.641 Y1.1 92.567,89.625 92.743,89.449 101.965,89.449 102.653,88.761 U2.4
OSC32_OUT: c14.2 U2.3 Y1.3 | length 11.7
  Top Layer w0.3: c14.2 97.003,93.158 Y1.3 99.206,93.123 103.068,89.261 U2.3
OSC_IN: c15.2 U2.5 Y2.3 | length 16.1
  Top Layer w0.3: c15.2 95.556,81.128 95.206,81.478 95.206,86.624 96.215,87.633 Y2.3 102.464,87.833 102.892,88.261 U2.5
OSC_OUT: c16.2 U2.6 Y2.1 | length 12.1
  Top Layer w0.3: Y2.1 96.407,83.273 c16.2 101.307,83.273 102.286,84.252 102.286,86.893 103.154,87.761 U2.6
PA0: J12.01 R10.2 U2.10 | length 37.8
  Top Layer w0.2: J12.01 v1(83.007,104.064) 83.007,99.18 R10.2 ; v3(102.946,85.776) 102.953,85.769 104.808,85.769 U2.10
  Bottom Layer w0.2: v1(83.007,104.064) 84.658,104.064 v3(102.946,85.776)
PA1: J11.3 U2.11 | length 31.9
  Top Layer w0.2: J11.3 79.718,100.952 81.928,100.952 v1(81.966,100.914) ; v1(102.946,84.988) 103.082,84.988 103.354,85.261 U2.11
  Bottom Layer w0.2: v1(81.966,100.914) 82.042,100.99 85.039,100.99 101.041,84.988 v1(102.946,84.988)
PA2: J5.2 R5.1 U2.12 | length 63.8
  Top Layer w0.2: v1(102.946,84.15) 102.983,84.15 103.313,84.48 104.198,84.48 104.315,84.598 104.315,84.711 104.365,84.761 U2.12
  Top Layer w0.3: v1(105.893,62.281) 105.931,62.243 105.931,60.16 J5.2
  Bottom Layer w0.3: v1(105.893,62.281) 105.893,64.745 106.731,65.583 106.731,69.621 101.016,75.336 101.016,82.22 v1(102.946,84.15) 103.886,83.21 117.373,83.21 120.015,85.852 v1(134.315,85.852) 134.311,85.856 134.311,87.042 R5.1
PA3: J5.1 R4.2 U2.13 | length 61.4
  Top Layer w0.3: v1(105.689,81.509) 106.315,82.134 U2.13 ; v1(108.433,62.433) 108.433,60.198 J5.1
  Bottom Layer w0.3: v1(105.689,81.509) 105.689,80.287 105.865,80.112 106.68,80.112 ; v1(108.433,62.433) 108.433,75.87 106.858,77.445 106.858,79.934 106.68,80.112 ; R4.2 139.386,87.189 139.386,85.963 v1(139.395,85.954) 133.553,80.112 106.68,80.112
PA4: R6.2 U2.14 | length 35.2
  Top Layer w0.3: v1(106.782,81.483) 106.815,81.517 U2.14
  Bottom Layer w0.3: v1(106.782,81.483) 106.782,80.795 106.957,80.62 130.505,80.62 v1(135.788,85.903) ; R6.2 135.792,87.169 135.792,85.906 v1@135.948,86.063
PA5: R8.1 U2.15 | length 52.3
  Top Layer w0.1: 107.315,80.975 U2.15
  Top Layer w0.2: v1(89.535,106.401) 89.535,107.536 R8.1
  Top Layer w0.3: v1(86.411,91.389) 86.411,94.31 89.535,97.434 v1(89.535,106.401) ; v2(99.593,79.68) 106.02,79.68 107.315,80.975
  Bottom Layer w0.3: v1(86.411,91.389) 87.274,91.389 89.357,89.306 90.477,89.306 90.653,89.131 90.653,80.188 92.304,78.537 96.444,78.537 97.587,79.68 v2(99.593,79.68)
PA6: J2.03 U2.16 | length 34
  Top Layer w0.3: U2.16 107.815,84.193 108.306,84.684 111.836,84.684 112.573,83.947 v1(114.122,83.947) ; v1(122.885,101.422) 122.898,101.435 125.031,101.435 J2.03
  Bottom Layer w0.3: v1(114.122,83.947) 116.967,83.947 119.939,86.919 122.225,86.919 122.885,87.579 v1(122.885,101.422)
PA7: J8.2 U2.17 | length 26.4
  Top Layer w0.2: v1(122.53,73.304) 122.568,73.266 125.133,73.266 J8.2
  Top Layer w0.3: v2(107.645,79.578) 107.645,80.597 108.28,81.232 v2(108.28,81.305) 108.315,81.34 U2.17
  Bottom Layer w0.1: v2(107.645,79.578) 107.753,79.578 107.982,79.807 117.162,79.807 117.221,79.748 117.221,76.2
  Bottom Layer w0.3: 117.221,76.2 120.117,73.304 v1(122.53,73.304)
PA8: J1.8 R3.1 U2.29 | length 67
  Top Layer w0.2: U2.29 114.904,86.761 115.087,86.944 v1(116.662,86.944) ; v1(116.637,78.461) 116.662,78.486 v1(116.662,84.633)
  Top Layer w0.3: R3.1 90.645,59.08 v1(91.846,59.08) ; v1(116.662,86.944) 122.522,92.804 J1.8
  Bottom Layer w0.2: v1(91.846,59.08) 114.554,59.08 116.637,61.163 v1(116.637,78.461) ; v1(116.662,84.633) v1(116.662,86.944)
PA9: J1.9 J2.01 U2.30 | length 29.9
  Top Layer w0.2: U2.30 115.989,87.261 116.154,87.427
  Top Layer w0.3: U2.30 U2.30@113.765,87.261 ; 116.154,87.427 123.531,94.804 124.666,94.804 124.83,94.64 J1.9 127.612,94.804 127.787,94.98 127.787,103.812 127.612,103.988 J2.01
PA10: J1.10 J2.02 U2.31 | length 25.4
  Top Layer w0.3: U2.31 115.066,87.761 123.907,96.602 124.791,96.602 J1.10 126.928,96.804 127.152,97.028 127.152,102.593 126.977,102.768 125.095,102.768 J2.02
PA11: J2.04 U2.32 | length 16.6
  Top Layer w0.2: U2.32 114.931,88.261 125.044,98.374
  Top Layer w0.3: 125.044,98.374 J2.04
PA12: J2.05 U2.33 | length 17.3
  Top Layer w0.2: U2.33 114.847,88.761 116.484,90.399 116.484,91.745 J2.05
PA15: J4.9 U2.38 | length 19.4
  Top Layer w0.3: U2.38 111.315,95.007 111.303,95.019 111.303,97.815 112.649,99.162 112.649,109.836 112.662,109.849 112.662,110.338 J4.9
PB0: O1.1 U2.18 | length 12
  Top Layer w0.3: U2.18 108.815,76.808 108.991,76.632 112.854,76.632 113.03,76.456 O1.1@113.03,75.286
PB1: R2.2 U2.19 | length 5.1
  Top Layer w0.2: U2.19 109.344,83.233 v2(109.344,79.277)
  Bottom Layer w0.2: v2(109.344,79.277) 109.36,79.277 109.644,78.992 R2.2
PB3: J4.8 U2.39 | length 19.7
  Top Layer w0.3: U2.39 110.815,97.988 111.912,99.085 111.912,107.454 110.864,108.502 J4.8
PB4: J4.7 U2.40 | length 20.2
  Top Layer w0.3: J4.7 108.864,108.915 111.328,106.451 111.328,99.339 110.315,98.326 U2.40
PB5: O1.7 U2.41 | length 25.8
  Top Layer w0.2: O1.7 97.79,76.235 97.907,76.352 101.632,76.352 101.746,76.467 101.746,77.235 v1(101.752,77.241) ; v1(103.073,81.559) 103.13,81.503 104.181,81.503 104.343,81.665 104.343,83.693 104.927,84.277 105.893,84.277 109.815,88.2 U2.41
  Bottom Layer w0.2: v1(101.752,77.241) 101.752,81.493 101.87,81.61 103.022,81.61 v1(103.073,81.559)
PB6: O1.2 U2.42 | length 33.9
  Top Layer w0.1: 104.877,83.39 105.51,84.023 106.35,84.023 110.338,88.011
  Top Layer w0.3: v1(104.242,80.645) 104.877,81.28 104.877,83.39 ; v1(106.655,76.149) 106.68,76.124 110.465,76.124 v2(110.49,76.098) O1.2 ; U2.42 109.315,93.205 109.576,93.465 v1(109.576,93.574) ; 110.338,88.011 110.338,88.468 113.284,91.415 v1(113.284,93.37)
  Bottom Layer w0.1: v1(104.242,80.645) 104.242,80.061 105.08,79.223 106.24,79.223 106.375,79.088 106.375,76.911 106.637,76.649 106.637,76.167 v1(106.655,76.149) ; 110.148,93.015 112.928,93.015 v1(113.284,93.37)
  Bottom Layer w0.3: v1(109.576,93.574) 109.589,93.574 110.148,93.015
PB7: J4.4 U2.43 | length 27.9
  Top Layer w0.2: J4.4 102.864,108.122 102.21,107.467 100.736,107.467 99.974,106.705 99.974,100.863 102.845,97.993 108.698,97.993 108.815,97.876 U2.43
PB8: J4.3 U2.45 | length 25.5
  Top Layer w0.2: J4.3 100.864,108.611 99.365,107.112 99.365,100.787 102.997,97.155 107.493,97.155 107.815,96.833 U2.45
PB9: J4.2 U2.46 | length 25.1
  Top Layer w0.2: J4.2 98.864,100.145 102.184,96.825 106.934,96.825 107.315,96.444 U2.46
PB10: J1.2 U2.21 | length 21.9
  Top Layer w0.2: U2.21 110.315,77.47 112.624,77.47
  Top Layer w0.3: 112.624,77.47 119.278,77.47 122.612,80.804 J1.2
PB11: J1.3 U2.22 | length 17.1
  Top Layer w0.2: U2.22 110.843,83.233 110.843,81.46 v1(110.871,81.432) ; v1(122.377,82.804) J1.3
  Bottom Layer w0.2: v1(110.871,81.432) 110.871,82.321 111.354,82.804 v1(122.377,82.804)
PB12: J9.2 U2.25 | length 50.4
  Top Layer w0.2: J9.2 82.372,110.541 82.372,108.534 v1(82.398,108.509) ; U2.25 114.234,84.761 114.388,84.607 v1(115.087,84.607)
  Bottom Layer w0.2: v1(82.398,108.509) 82.448,108.56 82.499,108.509 92.634,108.509 100.203,100.94 v1(100.203,95.987) 100.272,95.917 100.272,95.536 104.953,90.856 110.007,90.856 115.087,85.776 v1(115.087,84.607)
PB13: J1.5 U2.26 | length 12.3
  Top Layer w0.3: U2.26 118.383,85.261 119.926,86.804 J1.5
PB14: J1.6 U2.27 | length 12.9
  Top Layer w0.3: U2.27 117.206,85.761 120.249,88.804 J1.6
PB15: J1.7 U2.28 | length 13.6
  Top Layer w0.2: U2.28 116.894,86.261
  Top Layer w0.3: 116.894,86.261 121.436,90.804 J1.7
PC13: J4.1 U2.2 | length 24.6
  Top Layer w0.2: J4.1 96.864,100.748 102.692,94.92 102.692,90.932 103.863,89.761 U2.2
SWCLK: J7.2 U2.34 | length 28.6
  Top Layer w0.2: U2.34 113.35,89.296 114.341,89.296 v1(114.376,89.332) ; v1(122.606,108.56) 122.606,108.695 122.911,109 J7.2
  Bottom Layer w0.2: v1(114.376,89.332) 119.024,89.332 120.752,91.059 120.752,106.705 v1(122.606,108.56)
SWDIO: J7.3 U2.37 | length 27.3
  Top Layer w0.2: U2.37 111.815,92.728 111.938,92.851 v1(111.938,93.599) ; v1(120.142,108.534) 120.142,108.67 120.371,108.898 J7.3
  Bottom Layer w0.2: v1(111.938,93.599) 111.938,93.734 111.557,94.115 111.557,106.959 111.963,107.366 119.939,107.366 120.142,107.569 v1(120.142,108.534)
VBUS: c5.2 U1.3 | length 2.7
  Bottom Layer w0.3: U1.3 114.071,99.623 114.071,98.768 115.303,97.536 c5.2
pads on no net: J1.4 J4.5 J4.6 O1.9 O1.10 O1.11 O1.14 O1.15

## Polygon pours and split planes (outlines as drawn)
3V3 on Int2 (PWR) "3V3_L03_P001" (solid, pour order 1): 143.281,116.434 143.154,116.561 75.489,116.561 75.489,53.772 76.149,53.111 143.916,53.111 143.916,115.672 143.154,116.434
GND on Int1 (GND) "GND_L02_P006" (solid, pour order 6): 143.205,116.332 143.104,116.434 75.794,116.434 75.794,53.442 75.59,53.238 75.794,53.035 142.9,53.035 143.104,53.238 142.875,53.467 142.875,116.332

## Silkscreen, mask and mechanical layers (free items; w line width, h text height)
Top Overlay:
  drawing of 6 lines, arcs and shapes, not listed
  text "TEAM 7" at 129.709,113.547 h4 r315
